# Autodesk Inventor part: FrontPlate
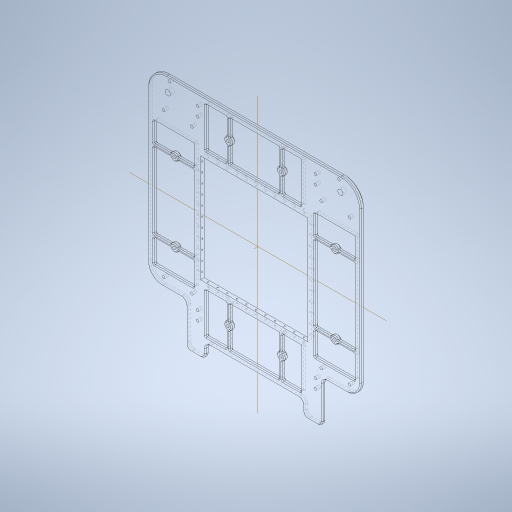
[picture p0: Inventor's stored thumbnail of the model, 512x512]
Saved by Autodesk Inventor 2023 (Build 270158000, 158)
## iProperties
Created: 2023-10
Part Number: FrontPlate
Material: Aluminum 7075
Document SubType Name: Modeling
Designer: tornqvih
Density: 2.81 g/cm^3
Appearance: Satin - Brushed Heavy
Mass: 1400.08 g
Surface Area: 1748.65 cm^2
Volume: 498.249 cm^3
Author: tornqvih
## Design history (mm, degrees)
sketch "Sketch1"
  geometry: L1 (-222, 222)-(222, 222); L2 (222, 222)-(222, -222); L3 (222, -222)-(-222, -222); L4 (-222, -222)-(-222, 222); L5 (-222, 222)-(222, -222); L6 (222, 222)-(-222, -222); L7 (0, -346.8)-(0, 316.8) reference; L8 (-310.8, 0)-(310.8, 0) reference; L9 (-142, -222)-(-102, -222); L10 (-102, -222)-(-102, -252); L11 (-102, -252)-(-142, -252); L12 (-142, -252)-(-142, -222); L13 (102, -222)-(142, -222); L14 (142, -222)-(142, -252); L15 (142, -252)-(102, -252); L16 (102, -252)-(102, -222); 2 further points
  constraints: 28 end point, 11 point on line, 4 parallel, 4 symmetric about line, 2 horizontal, 2 perpendicular, 2 other
  dimensions: "d0" = 444 distance of L5.start L6.start; "d1" = 444 distance of L6.end L5.start; "d108" = 40 distance of L10.end L11.end; "d109" = 30 distance of L11.end L9.start; "d110" = 80 distance between parallel lines of L4 L12
extrude "Extrusion1" new body sketch "Sketch1" distance "d4" = 8; taper "d5" = 0 deg
sketch "Sketch2"
  geometry: L1 (-112, -112)-(112, -112); L2 (112, -112)-(112, 112); L3 (112, 112)-(-112, 112); L4 (-112, 112)-(-112, -112); L5 (-112, -112)-(112, 112); L6 (112, -112)-(-112, 112); L7 (-102, 210)-(98, 210); L8 (98, 210)-(98, 126); L9 (98, 126)-(-102, 126); L10 (-102, 126)-(-102, 210); L11 (222, 222)-(-222, 222) reference; L12 (0, -346.8)-(0, 316.8) reference; L13 (-102, -126)-(98, -126); L14 (98, -126)-(98, -210); L15 (98, -210)-(-102, -210); L16 (-102, -210)-(-102, -126); L17 (-310.8, 0)-(310.8, 0) reference; L18 (-210, 127)-(-126, 127); L19 (-126, 127)-(-126, -133); L20 (-126, -133)-(-210, -133); L21 (-210, -133)-(-210, 127); L22 (-222, 222)-(-222, -222) reference; L23 (126, 127)-(210, 127); L24 (210, 127)-(210, -133); L25 (210, -133)-(126, -133); L26 (126, -133)-(126, 127); L27 (-222, -163)-(-142, -163); L28 (-142, -163)-(-142, -222); L29 (-142, -222)-(-222, -222); L30 (-222, -222)-(-222, -163); L31 (142, -163)-(222, -163); L32 (222, -163)-(222, -222); L33 (222, -222)-(142, -222); L34 (142, -222)-(142, -163); L35 (-222, -222)-(-142, -222) reference; 4 further points
  constraints: 60 end point, 12 symmetric about line, 8 parallel, 4 horizontal, 4 perpendicular, 2 midpoint
  dimensions: "d6" = 224 distance of L2.end L3.end; "d7" = 224 distance of L3.end L1.start; "d79" = 10 distance between parallel lines of L4 L10; "d80" = 200 distance between parallel lines of L8 L10; "d81" = 12 distance between parallel lines of L11 L7; "d82" = 14 distance between parallel lines of L3 L9; "d85" = 14 distance between parallel lines of L4 L19; "d86" = 12 distance between parallel lines of L22 L21; "d87" = 260 distance between parallel lines of L20 L18; "d88" = 15 distance between parallel lines of L3 L18; "d145" = 30 distance between parallel lines of L20 L27; "d146" = 0 distance between parallel lines of L35 L29; "d149" = 0 distance between parallel lines of L22 L30; "d150" = 80 distance between parallel lines of L30 L28
extrude "Extrusion2" cut sketch "Sketch2" distance "d8" = 8; taper "d9" = 0 deg
sketch "Sketch9"
  geometry: L1 (0, -346.8)-(0, 316.8) reference; L2 (-310.8, 0)-(310.8, 0) reference; L3 (98, 210)-(-102, 210) reference; L4 (-58, 210)-(-58, 126); L5 (-102, 126)-(98, 126) reference; L6 (-52, 210)-(-52, 126); L7 (52, 210)-(52, 126); L8 (-210, -133)-(-210, 127) reference; L9 (-210, 85)-(-126, 85); L10 (-126, -133)-(-126, 127) reference; L11 (-210, 79)-(-126, 79); L12 (-210, -79)-(-126, -79); L13 (-126, 127)-(-126, -133) reference; L14 (-102, 210)-(98, 210) reference; L15 (98, 126)-(-102, 126) reference; L16 (126, -79)-(210, -79); L17 (210, -85)-(126, -85); L18 (222, 222)-(-222, 222) reference; L19 (-222, 222)-(-222, -222) reference; L20 (58, 210)-(58, 126); L21 (126, -133)-(126, 127) reference; L22 (210, 127)-(210, -133) reference; L23 (-210, -85)-(-126, -85); L24 (126, 85)-(210, 85); L25 (126, 79)-(210, 79); L26 (-58, -126)-(-58, -210); L27 (-52, -126)-(-52, -210); L28 (52, -126)-(52, -210); L29 (58, -126)-(58, -210); L30 (98, -210)-(-102, -210) reference; L31 (-102, -126)-(98, -126) reference; C1 r 8 at (-167, 82); C2 r 8 at (-167, -82); C3 r 8 at (-55, 167); C4 r 8 at (55, 167); C5 r 8 at (167, 82); C6 r 8 at (167, -82); C7 r 8 at (-55, -167); C8 r 8 at (55, -167); 48 further points
  constraints: 32 end point, 30 symmetric about line, 10 point on line, 8 centre point, 7 equal radius, 2 horizontal, 2 vertical
  dimensions: "d115" = 16 diameter of C3; "d120" = 55 distance from line of L1 C3.centre; "d121" = 3 distance from line of C3.centre L4; "d123" = 3 distance from line of C3.centre L6; "d124" = 82 distance from line of L2 C1.centre; "d125" = 3 distance from line of C1.centre L9; "d126" = 3 distance from line of C1.centre L11; "d127" = 55 distance from line of L18 C3.centre; "d128" = 55 distance from line of L19 C1.centre
extrude "Extrusion4" join sketch "Sketch9" distance "d129" = 8; taper "d130" = 0 deg
sketch "Sketch3"
  geometry: L1 (-222, 222)-(-222, -222) reference; L2 (222, 222)-(-222, 222) reference; L3 (0, -346.8)-(0, 316.8) reference; L4 (-310.8, 0)-(310.8, 0) reference; L5 (-112, -112)-(-112, 112) reference; L6 (-222, -222)-(-142, -222) reference; L7 (112, 112)-(112, -112) reference; L8 (222, -222)-(222, 222) reference; L9 (112, -112)-(-112, -112) reference; 24 further points
  constraints: 10 horizontal alignment, 10 vertical alignment, 3 coincident
  dimensions: "d23" = 66 distance from line of L2 point (-189, 156); "d24" = 23 distance from line of L2 point (-118, 199); "d26" = 18 distance from line of L5 point (-130, 156); "d64" = 19 distance of point (-118, 180) point (-118, 199); "d66" = 33 distance from line of L6 point (-118, -189); "d67" = 19 distance of point (-118, -170) point (-118, -189); "d69" = 16 distance from line of L7 point (128, 180); "d70" = 23 distance from line of L8 point (199, 156); "d71" = 59 distance of point (199, 156) point (140, 156); "d72" = 6 horizontal distance of L5.end point (-118, 199); "d73" = 59 distance of point (-130, 156) point (-189, 156); "d74" = 34 distance from line of L9 point (-189, -146)
hole "Hole1" sketch "Sketch3" at (-118, 199), (-118, 180), (-130, 156), (-189, 156), (128, 199), (128, 180), (140, 156), (199, 156), (-118, -189), (-118, -170), (-130, -146), (-189, -146)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 diameter "d14" = 5.5; stored, may be unused: countersink angle "d18" = 90 deg, drill point angle "d20" = 118 deg; dims "d15" = 6, "d16" = 4, "d17" = 2, "d19" = 8
sketch "Sketch4"
  geometry: L1 (112, 9.6)-(112, -1.6) reference; L2 (334, 0)-(-110, 0) reference; 13 further points
  constraints: 5 horizontal alignment, 5 symmetric about line, 1 midpoint
  dimensions: "d28" = 4 distance from line of L2 point (12, 4); "d29" = 20 distance from line of L1 point (92, 4); "d30" = 60 distance from line of L1 point (52, 4); "d31" = 100 distance from line of L1 point (12, 4); "d170" = 40 distance from line of L1 point (72, 4); "d171" = 80 distance from line of L1 point (32, 4)
hole "Hole2" sketch "Sketch4" at (12, 4), (52, 4), (92, 4), (132, 4), (172, 4), (212, 4), (32, 4), (72, 4), (112, 4), (152, 4), (192, 4) diameter "d32" = 2.459; stored, may be unused: countersink angle "d36" = 90 deg, drill point angle "d38" = 118 deg; dims "d33" = 6, "d34" = 4, "d35" = 2, "d37" = 8.8
sketch "Sketch5"
  geometry: L1 (9.6, 112)-(-1.6, 112) reference; L2 (8, -51)-(8, 334) reference; 13 further points
  constraints: 5 symmetric about line, 5 vertical alignment, 1 midpoint
  dimensions: "d39" = 4 distance from line of L2 point (4, 212); "d40" = 20 distance from line of L1 point (4, 132); "d41" = 60 distance from line of L1 point (4, 172); "d42" = 100 distance from line of L1 point (4, 212); "d172" = 40 distance from line of L1 point (4, 152); "d173" = 80 distance from line of L1 point (4, 192)
hole "Hole3" sketch "Sketch5" at (4, 212), (4, 172), (4, 132), (4, 92), (4, 52), (4, 12), (4, 192), (4, 152), (4, 112), (4, 72), (4, 32) diameter "d43" = 2.459; stored, may be unused: countersink angle "d47" = 90 deg, drill point angle "d49" = 118 deg; dims "d44" = 6, "d45" = 4, "d46" = 2, "d48" = 8.8
sketch "Sketch6"
  geometry: C1 r 1.23 at (12, -4) reference; C2 r 1.23 at (52, -4) reference; C3 r 1.23 at (92, -4) reference; C4 r 1.23 at (132, -4) reference; C5 r 1.23 at (172, -4) reference; C6 r 1.23 at (212, -4) reference; C7 r 1.23 at (32, -4) reference; C8 r 1.23 at (72, -4) reference; C9 r 1.23 at (112, -4) reference; C10 r 1.23 at (152, -4) reference; C11 r 1.23 at (192, -4) reference; 12 further points
  constraints: 11 coincident
hole "Hole4" sketch "Sketch6" at (12, -4), (52, -4), (92, -4), (132, -4), (172, -4), (212, -4), (32, -4), (72, -4), (112, -4), (152, -4), (192, -4) diameter "d50" = 2.459; stored, may be unused: countersink angle "d54" = 90 deg, drill point angle "d56" = 118 deg; dims "d51" = 6, "d52" = 4, "d53" = 2, "d55" = 8.8
sketch "Sketch7"
  geometry: C1 r 1.23 at (-4, 212) reference; C2 r 1.23 at (-4, 172) reference; C3 r 1.23 at (-4, 132) reference; C4 r 1.23 at (-4, 92) reference; C5 r 1.23 at (-4, 52) reference; C6 r 1.23 at (-4, 12) reference; C7 r 1.23 at (-4, 192) reference; C8 r 1.23 at (-4, 152) reference; C9 r 1.23 at (-4, 112) reference; C10 r 1.23 at (-4, 72) reference; C11 r 1.23 at (-4, 32) reference; 12 further points
  constraints: 11 coincident
hole "Hole5" sketch "Sketch7" at (-4, 212), (-4, 172), (-4, 132), (-4, 92), (-4, 52), (-4, 12), (-4, 192), (-4, 152), (-4, 112), (-4, 72), (-4, 32) diameter "d57" = 2.459; stored, may be unused: countersink angle "d61" = 90 deg, drill point angle "d63" = 118 deg; dims "d58" = 6, "d59" = 4, "d60" = 2, "d62" = 8.8
sketch "Sketch8"
  geometry: L1 (222, 222)-(-222, 222) reference; L2 (0, -346.8)-(0, 316.8) reference; 4 further points
  constraints: 1 symmetric about line
  dimensions: "d97" = 30 distance from line of L1 point (-180, 192); "d98" = 180 distance from line of L2 point (-180, 192)
hole "Hole6" sketch "Sketch8" at (-180, 192), (180, 192) diameter "d99" = 10.5; stored, may be unused: countersink angle "d103" = 90 deg, drill point angle "d105" = 118 deg; dims "d100" = 6, "d101" = 4, "d102" = 2, "d104" = 8
sketch "Sketch11"
  geometry: L1 (0, -346.8)-(0, 316.8) reference; L2 (222, 222)-(-222, 222) reference; 3 further points
  constraints: 1 symmetric about line
  dimensions: "d154" = 177 distance from line of L1 point (-177, 214); "d155" = 8 distance from line of L2 point (-177, 214)
hole "Hole7" sketch "Sketch11" at (-177, 214), (177, 214) diameter "d156" = 5.5; stored, may be unused: countersink angle "d160" = 90 deg, drill point angle "d162" = 118 deg; dims "d157" = 6, "d158" = 4, "d159" = 2, "d161" = 8
sketch "Sketch12"
  geometry: A1 r 8 centre (-55, 167) between (-52, 159.584) and (-52, 174.416) reference; A2 r 8 centre (55, 167) between (52, 174.416) and (52, 159.584) reference; A3 r 8 centre (-167, 82) between (-174.416, 79) and (-159.584, 79) reference; A4 r 8 centre (-167, -82) between (-174.416, -85) and (-159.584, -85) reference; A5 r 8 centre (167, 82) between (159.584, 79) and (174.416, 79) reference; A6 r 8 centre (167, -82) between (174.416, -79) and (159.584, -79) reference; A7 r 8 centre (-55, -167) between (-58, -159.584) and (-58, -174.416) reference; A8 r 8 centre (55, -167) between (52, -159.584) and (52, -174.416) reference; 9 further points
  constraints: 8 coincident
hole "Hole8" sketch "Sketch12" at (-55, 167), (55, 167), (-167, 82), (-167, -82), (167, 82), (167, -82), (-55, -167), (55, -167) diameter "d163" = 5.5; stored, may be unused: countersink angle "d167" = 90 deg, drill point angle "d169" = 118 deg; dims "d164" = 6, "d165" = 4, "d166" = 2, "d168" = 8
fillet "Fillet2" dims "d131" = 10, "d135" = 2, "d136" = 2, "d137" = 2, "d138" = 2, "d148" = 30, "d151" = 40
chamfer "Chamfer3" distance "d139" = 2; stored, may be unused: second distance "d140" = 2, angle "d141" = 45 deg
chamfer "Chamfer4" distance "d142" = 2; stored, may be unused: second distance "d143" = 2, angle "d144" = 45 deg
node "FrontPlate"
